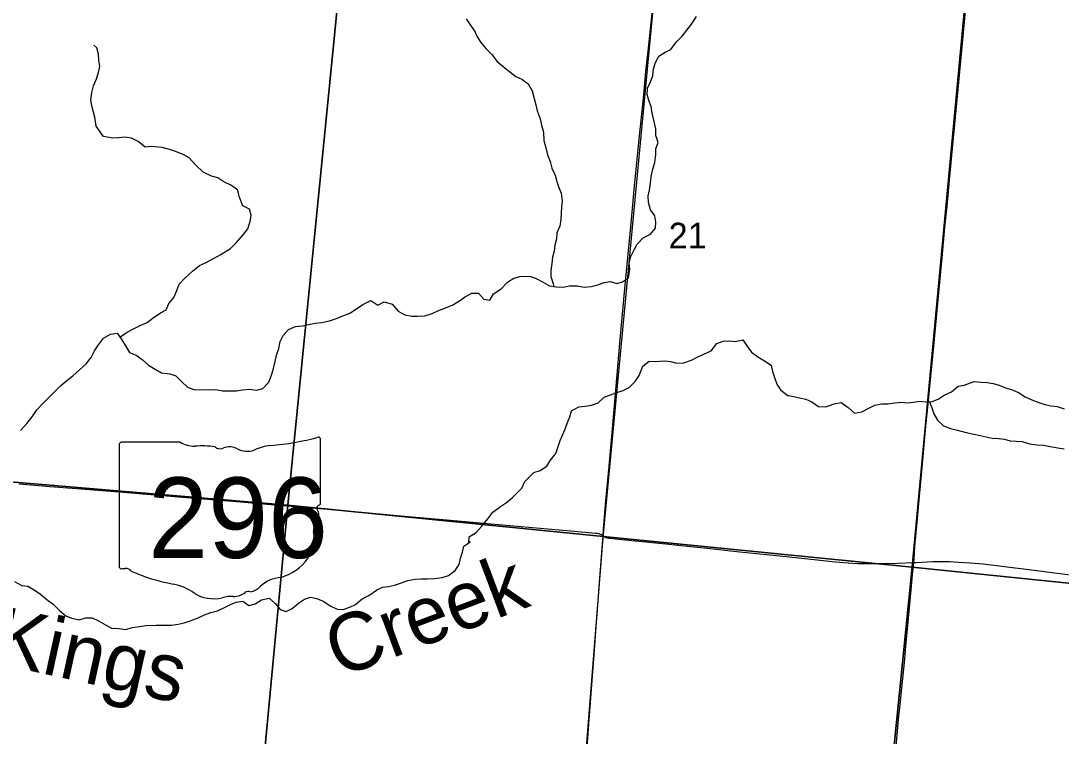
# Model space of a CAD drawing. Extents: x 0 to 1067, y 0 to 440.
# Drawn here: x 801.512 to 803.215, y 355.137 to 356.309 of the extents above; entities that cross this region are included whole.
import ezdxf

# ---------------------------------------------------------------- set-up
doc = ezdxf.new("R2010")
doc.units = 0
for name, color, linetype in [('GM_X_Minor_River', 7, 'Continuous'), ('GM_X_Minor_River_Text', 7, 'Continuous'), ('GM_X_Rail_Line', 7, 'Continuous'), ('GM_X_Section', 7, 'Continuous'), ('GM_X_Section_Text', 7, 'Continuous'), ('GM_X_State_Location', 7, 'Continuous'), ('GM_X_State_Route', 7, 'Continuous'), ('GM_X_State_Shield', 7, 'Continuous'), ('GM_X_Township_Road', 7, 'Continuous'), ('GM_X_US_Route', 7, 'Continuous')]:
    doc.layers.add(name, color=color, linetype=linetype)

msp = doc.modelspace()

# ---------------------------------------------------------------- linework, layer by layer
at = {"layer": 'GM_X_Minor_River'}
for points in [[(802.2582, 356.2838), (802.2559, 356.2915), (802.2482, 356.302), (802.2417, 356.3121)], [(802.2502, 355.8625), (802.261, 355.8625), (802.27, 355.8525), (802.2799, 355.8509), (802.2854, 355.8615), (802.298, 355.8698), (802.3084, 355.8807), (802.3187, 355.8871), (802.329, 355.89), (802.345, 355.8903), (802.3556, 355.8867), (802.3659, 355.8813), (802.3772, 355.8744), (802.3883, 355.8727), (802.3997, 355.8726), (802.41, 355.8748), (802.4229, 355.8747), (802.4339, 355.8723), (802.4454, 355.8733), (802.4564, 355.8763), (802.4667, 355.88), (802.4767, 355.8814), (802.4873, 355.8783), (802.4968, 355.8809), (802.5064, 355.8876), (802.5088, 355.9021), (802.5078, 355.9116), (802.5102, 355.9226), (802.516, 355.9336), (802.521, 355.9431), (802.5306, 355.9533), (802.5425, 355.9593), (802.5509, 355.9691), (802.5514, 355.9794), (802.55, 355.9893), (802.5428, 355.9989), (802.5391, 356.0111), (802.5388, 356.0218), (802.5408, 356.0313), (802.5428, 356.0427), (802.5437, 356.0538), (802.5465, 356.0655), (802.5496, 356.0766), (802.5516, 356.0895), (802.5513, 356.099), (802.5552, 356.1096), (802.5515, 356.1211), (802.5516, 356.1318), (802.5487, 356.1436), (802.5454, 356.1577), (802.544, 356.1684), (802.5398, 356.178), (802.5373, 356.1883), (802.5377, 356.1985), (802.5428, 356.2088), (802.5463, 356.2186), (802.5475, 356.2301), (802.5507, 356.2407), (802.5565, 356.2509), (802.5665, 356.2573), (802.576, 356.2618), (802.5849, 356.2739), (802.5945, 356.2837), (802.6099, 356.3033), (802.618, 356.3158)], [(801.6742, 355.7903), (801.6843, 355.7975), (801.6944, 355.8029), (801.7075, 355.8097), (801.7186, 355.8143), (801.7287, 355.8224), (801.7403, 355.8301), (801.75, 355.8355), (801.7544, 355.8456), (801.7623, 355.8553), (801.7672, 355.8669), (801.7713, 355.8771), (801.7803, 355.8871), (801.7932, 355.8985), (801.8045, 355.9081), (801.8144, 355.912), (801.8272, 355.9196), (801.8395, 355.9257), (801.855, 355.9359), (801.8648, 355.9455), (801.8761, 355.9581), (801.8836, 355.9682), (801.8874, 355.9802), (801.8888, 355.9901), (801.8865, 356), (801.8756, 356.0057), (801.8696, 356.0211), (801.8669, 356.0311), (801.8569, 356.039), (801.8445, 356.0447), (801.8345, 356.0514), (801.8243, 356.054), (801.8105, 356.0609), (801.7979, 356.0727), (801.7876, 356.084), (801.7775, 356.09), (801.7651, 356.0946), (801.7554, 356.0979), (801.7433, 356.1013), (801.7251, 356.1026), (801.7153, 356.1018), (801.7038, 356.1112), (801.6933, 356.1165), (801.6823, 356.1183), (801.6721, 356.1171), (801.6626, 356.1167), (801.6475, 356.119), (801.6351, 356.1361), (801.6328, 356.151), (801.6288, 356.1675), (801.6264, 356.179), (801.6279, 356.1915), (801.6309, 356.202), (801.6358, 356.2137), (801.6391, 356.2239), (801.6413, 356.2344), (801.6397, 356.2444), (801.6389, 356.2543), (801.6361, 356.2643), (801.6317, 356.269)], [(802.2582, 356.2838), (802.265, 356.2731), (802.2733, 356.2635), (802.2828, 356.2535), (802.2918, 356.2423), (802.3016, 356.2339), (802.3122, 356.2254), (802.3224, 356.2177), (802.3319, 356.213), (802.3425, 356.2053), (802.3492, 356.1938), (802.3514, 356.1839), (802.3547, 356.1709), (802.3569, 356.161), (802.3618, 356.1484), (802.3643, 356.1377), (802.3677, 356.1263), (802.3683, 356.1125), (802.3713, 356.1007), (802.3738, 356.0892), (802.3783, 356.0782), (802.3809, 356.0675), (802.3865, 356.0556), (802.3894, 356.0457), (802.3928, 356.0357), (802.3965, 356.0262), (802.3979, 356.014), (802.397, 356.0041), (802.3966, 355.9934), (802.3957, 355.9835), (802.3945, 355.9721), (802.3894, 355.9615), (802.3886, 355.9516), (802.3858, 355.9413), (802.385, 355.9314), (802.3822, 355.9216), (802.3814, 355.9109), (802.3794, 355.8999), (802.3796, 355.8899), (802.3833, 355.8777), (802.3843, 355.8733)], [(801.5116, 355.6374), (801.5218, 355.6489), (801.5304, 355.6597), (801.538, 355.6713), (801.5485, 355.6824), (801.5583, 355.692), (801.5677, 355.7016), (801.5775, 355.7112), (801.5872, 355.7197), (801.5973, 355.727), (801.6191, 355.7469), (801.627, 355.7573), (801.6326, 355.7682), (801.639, 355.7779), (801.6473, 355.7891), (801.6589, 355.7952), (801.6699, 355.7968), (801.6772, 355.7859), (801.6833, 355.7762), (801.6899, 355.7653), (801.7007, 355.7608), (801.7108, 355.7537), (801.7211, 355.7446), (801.7316, 355.7382), (801.7424, 355.7322), (801.7556, 355.7303), (801.7654, 355.7273), (801.775, 355.7179), (801.7846, 355.7088), (801.7951, 355.7047), (801.8209, 355.704), (801.8304, 355.7048), (801.8421, 355.7026), (801.8539, 355.7026), (801.8649, 355.7026), (801.8748, 355.7043), (801.8862, 355.7051), (801.8979, 355.7036), (801.9079, 355.7063), (801.9177, 355.7167), (801.9222, 355.7283), (801.9255, 355.7389), (801.9281, 355.7506), (801.9303, 355.7612), (801.9341, 355.7718), (801.9363, 355.7831), (801.9415, 355.7932), (801.9502, 355.8033), (801.9613, 355.8079), (801.9723, 355.8091), (801.9827, 355.8114), (801.9945, 355.8134), (802.0048, 355.8146), (802.017, 355.8173), (802.0285, 355.8211), (802.0392, 355.8254), (802.0507, 355.83), (802.0612, 355.8369), (802.0717, 355.8442), (802.0847, 355.8503), (802.0963, 355.8431), (802.1067, 355.8485), (802.1199, 355.8443), (802.1294, 355.8329), (802.1406, 355.8269), (802.1519, 355.8247), (802.1614, 355.8251), (802.1732, 355.8252), (802.1851, 355.829), (802.1947, 355.8337), (802.2089, 355.839), (802.2193, 355.8436), (802.2301, 355.8501), (802.2398, 355.8571), (802.2502, 355.8625), (802.2494, 355.8633)], [(802.2451, 355.4535), (802.246, 355.4632), (802.2571, 355.4704), (802.266, 355.4802), (802.2764, 355.4927), (802.2844, 355.5036), (802.2971, 355.5131), (802.307, 355.5194), (802.3166, 355.5277), (802.332, 355.5432), (802.3367, 355.5538), (802.3517, 355.5686), (802.3623, 355.5723), (802.3727, 355.5794), (802.3792, 355.5889), (802.3877, 355.5999), (802.3948, 355.6212), (802.4025, 355.6386), (802.4068, 355.6504), (802.4107, 355.6599), (802.4135, 355.6698), (802.4253, 355.6761), (802.4349, 355.6772), (802.4463, 355.679), (802.457, 355.6827), (802.467, 355.6921), (802.4773, 355.6958), (802.4876, 355.6999), (802.4979, 355.7029), (802.5075, 355.7081), (802.5178, 355.7179), (802.524, 355.7278), (802.5302, 355.743), (802.5406, 355.7513), (802.5505, 355.7504), (802.5654, 355.7518), (802.5756, 355.7506), (802.5855, 355.7478), (802.5973, 355.7485), (802.6095, 355.7529), (802.6199, 355.7585), (802.6313, 355.763), (802.642, 355.7682), (802.6513, 355.78), (802.6616, 355.7837), (802.6719, 355.7843), (802.6814, 355.7835), (802.6936, 355.786), (802.7004, 355.7761), (802.7079, 355.7657), (802.7181, 355.758), (802.7295, 355.7518), (802.74, 355.7445), (802.7422, 355.7341), (802.7456, 355.7242), (802.7497, 355.7135), (802.7561, 355.7035), (802.7674, 355.6947), (802.7773, 355.6934), (802.7868, 355.691), (802.7967, 355.6891), (802.8069, 355.6844), (802.8175, 355.6767), (802.8297, 355.6762), (802.8434, 355.681), (802.8545, 355.6832), (802.8662, 355.6751), (802.8764, 355.6662), (802.8886, 355.6684), (802.9001, 355.6744), (802.9097, 355.6788), (802.9215, 355.681), (802.9314, 355.6813), (802.9428, 355.6827), (802.9527, 355.6838), (802.9634, 355.6829), (802.9729, 355.684), (802.9828, 355.6854), (802.9923, 355.6845), (803.0037, 355.6848), (803.0137, 355.6889), (803.0233, 355.6957), (803.0355, 355.7009), (803.0462, 355.71), (803.0562, 355.7121), (803.0726, 355.7181), (803.0832, 355.7165), (803.0939, 355.716), (803.1038, 355.7144), (803.1133, 355.7116), (803.1239, 355.7077), (803.1334, 355.7046), (803.1451, 355.6999), (803.1561, 355.6929), (803.1671, 355.6879), (803.1781, 355.6836), (803.188, 355.68), (803.1982, 355.678), (803.2085, 355.6768), (803.2195, 355.6729)], [(802.9994, 355.6847), (803.0033, 355.6749), (803.0066, 355.6646), (803.0122, 355.6543), (803.0224, 355.645), (803.0338, 355.6411), (803.0452, 355.6379), (803.0596, 355.6344), (803.0718, 355.6316), (803.0824, 355.6292), (803.1018, 355.6248), (803.1125, 355.6243), (803.122, 355.6235), (803.1315, 355.6207), (803.141, 355.6203), (803.1509, 355.6198), (803.163, 355.6159), (803.1752, 355.6142), (803.1862, 355.6137), (803.1969, 355.6114), (803.2094, 355.609), (803.2197, 355.6073)], [(801.6603, 355.3135), (801.6725, 355.3132), (801.6838, 355.3113), (801.6942, 355.3148), (801.7067, 355.3163), (801.7167, 355.3183), (801.7334, 355.3186), (801.7459, 355.3186), (801.7588, 355.3186), (801.7695, 355.3202), (801.7794, 355.3222), (801.789, 355.3257), (801.8009, 355.3303), (801.8128, 355.3353), (801.8228, 355.3392), (801.8338, 355.3419), (801.8442, 355.3473), (801.855, 355.3527), (801.8646, 355.3562), (801.8753, 355.3578), (801.885, 355.3506), (801.8957, 355.3534), (801.9061, 355.3599), (801.9187, 355.3629), (801.9283, 355.3543), (801.9364, 355.3445), (801.9465, 355.3412), (801.9562, 355.3458), (801.9663, 355.3547), (801.9763, 355.3612), (801.9859, 355.3644), (801.9965, 355.3625), (802.0077, 355.3576), (802.0181, 355.3505), (802.0297, 355.3448), (802.0396, 355.3445), (802.0503, 355.3484), (802.06, 355.3526), (802.0709, 355.3618), (802.0816, 355.3672), (802.094, 355.376), (802.1037, 355.3807), (802.1136, 355.3819), (802.1235, 355.3843), (802.135, 355.3881), (802.1454, 355.392), (802.1572, 355.3939), (802.1674, 355.3944), (802.1773, 355.3948), (802.1895, 355.3949), (802.2017, 355.3968), (802.212, 355.3999), (802.2229, 355.408), (802.2296, 355.418), (802.2314, 355.4283), (802.2351, 355.438), (802.2369, 355.4479), (802.247, 355.4548), (802.2474, 355.456)], [(801.5017, 355.3902), (801.5136, 355.3838), (801.5235, 355.3823), (801.5339, 355.3763), (801.5439, 355.3692), (801.5547, 355.3605), (801.5651, 355.3533), (801.5758, 355.3423), (801.5858, 355.334), (801.5956, 355.3303), (801.6076, 355.3273), (801.6176, 355.3304), (801.6286, 355.3308), (801.6391, 355.3256), (801.6503, 355.3192), (801.6603, 355.3135)]]:
    msp.add_lwpolyline(points, dxfattribs=at)
at = {"layer": 'GM_X_Rail_Line'}
msp.add_lwpolyline([(802.2568, 353.3753), (802.2686, 353.4388), (802.2775, 353.5048), (802.3214, 353.8784), (802.3514, 354.1458), (802.3864, 354.4639), (802.4092, 354.7535), (802.4654, 355.4621), (802.5612, 356.4781), (802.6578, 357.3836), (802.6646, 357.4719), (802.676, 357.6021)], dxfattribs=at)
at = {"layer": 'GM_X_Section'}
for points in [[(800.9985, 356.6154), (802.0488, 356.5225), (801.949, 355.5154), (800.8971, 355.6038)], [(803.0664, 356.4332), (802.9708, 355.4138), (801.949, 355.5154), (802.0488, 356.5225)], [(803.0664, 356.4332), (804.1217, 356.3334), (804.0106, 355.307), (802.9708, 355.4138)], [(800.8971, 355.6038), (801.949, 355.5154), (801.8528, 354.4938), (800.8205, 354.5819)], [(801.949, 355.5154), (802.9708, 355.4138), (802.8724, 354.4357), (801.8528, 354.4938)], [(804.0106, 355.307), (803.9043, 354.3108), (802.8724, 354.4357), (802.9708, 355.4138)]]:
    msp.add_lwpolyline(points, close=True, dxfattribs=at)
at = {"layer": 'GM_X_State_Route'}
for points in [[(801.5093, 355.5502), (801.5601, 355.546), (801.6245, 355.5407), (801.6796, 355.5365), (801.783, 355.5279), (801.8592, 355.5217), (801.9279, 355.516), (802.014, 355.5086), (802.0938, 355.5014), (802.1341, 355.4979), (802.2213, 355.4899), (802.3123, 355.4821), (802.4119, 355.473), (802.4528, 355.4695), (802.4555, 355.4692), (802.4579, 355.4687), (802.4601, 355.4679), (802.462, 355.467), (802.4653, 355.465)], [(802.4653, 355.465), (802.4678, 355.4633), (802.4697, 355.4624), (802.4718, 355.4618), (802.4743, 355.4613), (802.4772, 355.461), (802.485, 355.4602), (802.5401, 355.4547), (802.5679, 355.4517), (802.6081, 355.4475), (802.6353, 355.4447), (802.689, 355.4389), (802.7545, 355.4322), (802.8157, 355.4255), (802.8447, 355.4226), (802.8664, 355.4206), (802.8819, 355.4199), (802.8994, 355.4196), (802.9242, 355.4196), (802.9472, 355.4202), (802.9737, 355.4214)], [(802.9737, 355.4214), (802.9777, 355.4215), (803.005, 355.4227), (803.0192, 355.4229), (803.0322, 355.4227), (803.0471, 355.4221), (803.0657, 355.4208), (803.0873, 355.4189), (803.1132, 355.416), (803.1706, 355.4088), (803.2384, 355.4001), (803.3031, 355.392), (803.3425, 355.3867), (803.3991, 355.379), (803.4428, 355.373), (803.4712, 355.3694), (803.4892, 355.3672)]]:
    msp.add_lwpolyline(points, dxfattribs=at)
at = {"layer": 'GM_X_State_Shield'}
for p, q in [((802.0026, 355.5185), (802.0026, 355.6232)), ((801.673, 355.6148), (801.673, 355.4147)), ((801.7728, 355.6182), (801.6763, 355.6182)), ((802.0026, 355.5185), (802.0026, 355.5185))]:
    msp.add_line(p, q, dxfattribs=at)
for centre, major_axis, start_param, end_param in [((801.8852, 355.8911), (0.3495, 0), 4.814394, 5.042369), ((801.999, 355.6236), (0.00367, 0), 6.141152, 7.989035), ((801.6768, 355.6152), (0.00382, 0), 1.712693, 3.28349), ((801.7958, 355.6415), (0.037, 0), 4.042523, 4.731795), ((801.8081, 355.5059), (0.133, 0), 1.404758, 1.657858), ((801.8383, 355.6162), (0.0107, 0), 3.836095, 5.185415), ((801.8539, 355.5931), (0.0222, 0), 0.950623, 2.079405), ((801.8826, 355.6248), (0.0267, 0), 4.081561, 5.145723), ((801.9298, 355.5571), (0.0703, 0), 1.699011, 2.107814), ((802.0018, 355.5108), (0.00568, 0), 1.883978, 3.671073), ((801.9657, 355.4976), (0.0341, 0), 5.934695, 6.695948), ((801.9987, 355.5181), (0.00393, 0), 5.05454, 6.418171), ((802.0158, 355.4747), (0.0248, 0), 2.387724, 3.262537), ((801.9048, 355.4614), (0.0874, 0), 5.101752, 6.440018), ((801.6769, 355.4142), (0.00385, 0), 3.00124, 4.508301), ((801.6774, 355.4347), (0.0294, 0), 4.665946, 4.897461), ((801.6835, 355.4031), (0.0106, 0), 0.519207, 1.627899), ((801.8173, 355.5829), (0.2524, 0), 4.195997, 4.488961), ((801.742, 355.3248), (0.079, 0), 0.823519, 1.323587), ((801.9417, 355.3585), (0.0479, 0), 1.647645, 2.488434), ((801.8274, 355.4021), (0.0501, 0), 4.026481, 4.996735), ((801.8564, 355.3329), (0.0412, 0), 1.495662, 1.94098), ((801.8601, 355.3871), (0.0267, 0), 4.691044, 5.507374), ((801.8842, 355.3678), (0.00752, 0), 1.147584, 2.315152), ((801.881, 355.3953), (0.0282, 0), 4.937069, 5.64225)]:
    msp.add_ellipse(centre, major_axis=major_axis, ratio=0.8, start_param=start_param, end_param=end_param, dxfattribs=at)
at = {"layer": 'GM_X_Township_Road'}
for points in [[(802.9737, 355.4214), (802.9741, 355.4275), (802.9756, 355.4473), (802.9791, 355.4869), (802.9824, 355.524), (802.9856, 355.5587), (802.9889, 355.5952), (802.9929, 355.6391), (802.9975, 355.6861), (803, 355.7102), (803.0057, 355.7696), (803.0114, 355.8283), (803.0152, 355.8691), (803.0199, 355.9205), (803.0247, 355.9706), (803.028, 356.0052), (803.033, 356.0597), (803.0373, 356.1048), (803.0463, 356.197), (803.0514, 356.2489), (803.0546, 356.2835), (803.059, 356.3311)], [(802.9437, 355.1089), (802.9473, 355.151), (802.9487, 355.1648), (802.9507, 355.1833), (802.9541, 355.2153), (802.9587, 355.2629), (802.9607, 355.2845), (802.9645, 355.3241), (802.9695, 355.3767), (802.9717, 355.4013), (802.9737, 355.4214)]]:
    msp.add_lwpolyline(points, dxfattribs=at)
at = {"layer": 'GM_X_US_Route'}
for points in [[(802.4653, 355.465), (802.4659, 355.4756), (802.4692, 355.5162), (802.4749, 355.5793), (802.4793, 355.6276), (802.4876, 355.7229), (802.4927, 355.7805), (802.4984, 355.8461), (802.5016, 355.8814), (802.5103, 355.9711), (802.5166, 356.0379), (802.5241, 356.1146), (802.5315, 356.1875), (802.5352, 356.2258), (802.5391, 356.2642), (802.5546, 356.4099)], [(802.4351, 355.0643), (802.4418, 355.157), (802.4469, 355.228), (802.4505, 355.2707), (802.4543, 355.3234), (802.4551, 355.3364), (802.4598, 355.3959), (802.4646, 355.4584), (802.4653, 355.465)]]:
    msp.add_lwpolyline(points, dxfattribs=at)

# ---------------------------------------------------------------- texts
at = {"layer": 'GM_X_Minor_River_Text'}
for s, height, rotation, p in [('Creek', 0.09469, 20.6145, (802.0327, 355.2317)), ('Kings', 0.0947, 347.6289, (801.4615, 355.2582))]:
    msp.add_text(s, height=height, rotation=rotation, dxfattribs=at).set_placement(p)
at = {"layer": 'GM_X_Section_Text'}
msp.add_text('21', height=0.04186, rotation=0, dxfattribs=at).set_placement((802.5723, 355.9361))
at = {"layer": 'GM_X_State_Location'}
msp.add_text('296', height=0.000189, rotation=0, dxfattribs=at).set_placement((801.7673, 355.4876))
for s in ['s', 'r']:
    msp.add_text(s, height=0.000189, dxfattribs=at).set_placement((801.8341, 355.5014))
at = {"layer": 'GM_X_State_Shield'}
msp.add_text('296', height=0.13184, dxfattribs=at).set_placement((801.7205, 355.4288))

doc.saveas('drawing.dxf')
